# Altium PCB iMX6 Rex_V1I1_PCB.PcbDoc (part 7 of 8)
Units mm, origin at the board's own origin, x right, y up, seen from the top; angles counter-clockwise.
Board outline 70 x 40 mm, 12 copper layers (L1, L2, L3, L4, L5 (PWR), L6 (PWR), L7 (PWR), L8 (PWR), L9, L10, L11, L12), stack 1.566 mm thick; 473 components, 409 nets, 2294 pads, 1880 vias.
Unrouted connection lines stored in the file: 7.
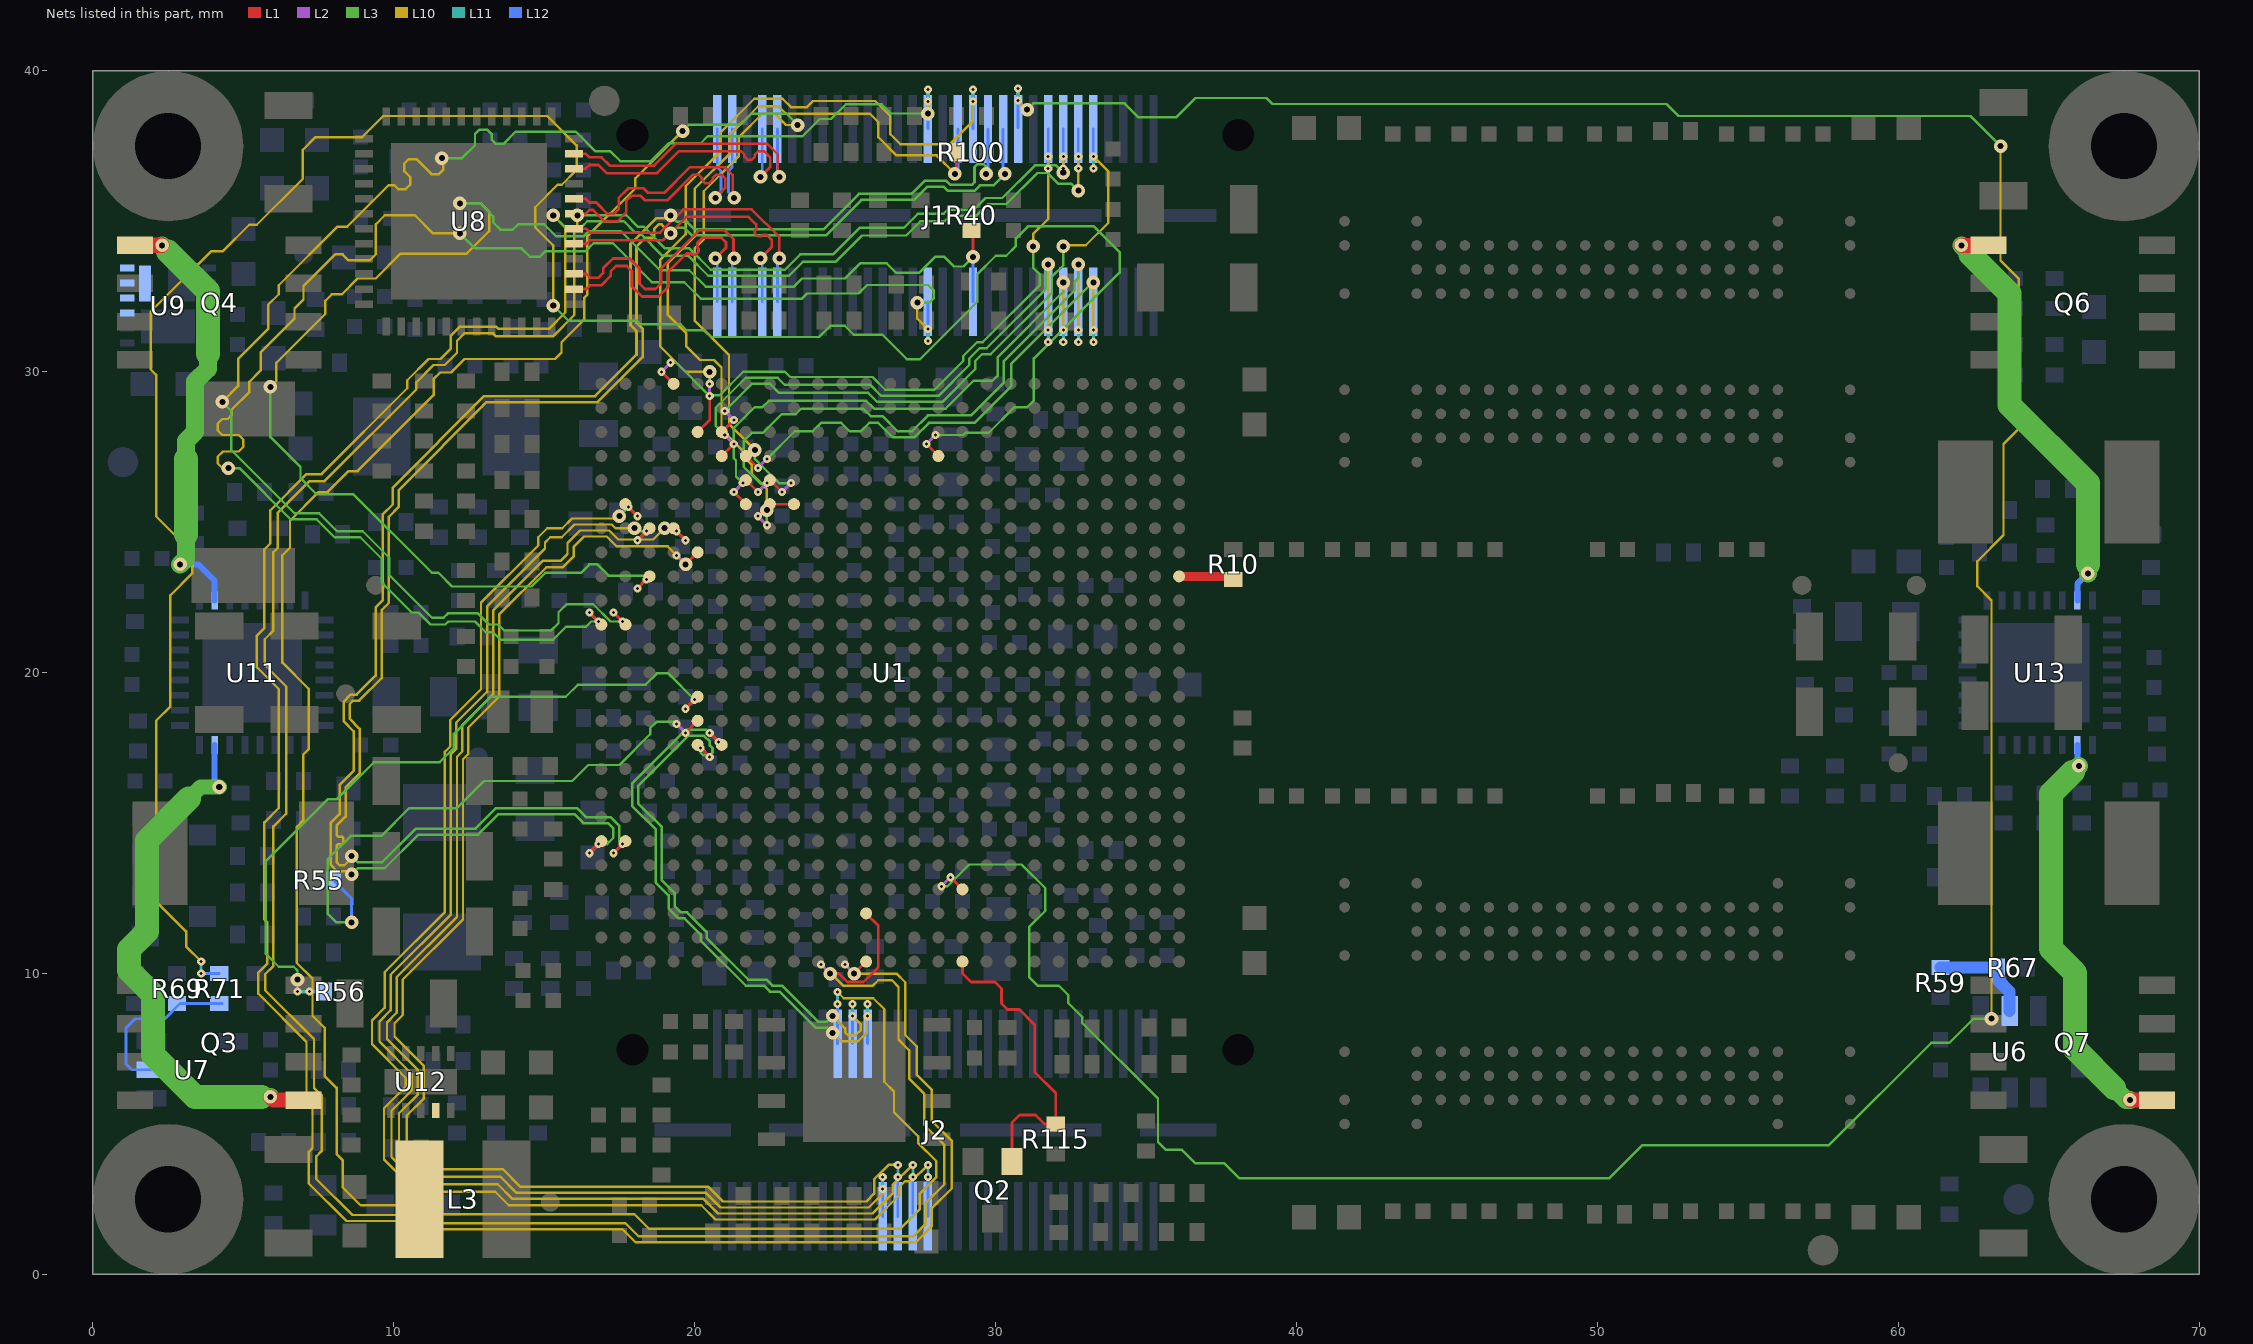
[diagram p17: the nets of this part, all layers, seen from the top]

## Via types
v1: diameter 0.45, hole 0.2, L1 to L12, tented both sides, 761 vias
v2: diameter 0.27, hole 0.1, L1 to L2, 305 vias
v3: diameter 0.27, hole 0.1, L2 to L3, 290 vias
v4: diameter 0.45, hole 0.2, L3 to L10, 196 vias
v5: diameter 0.27, hole 0.1, L11 to L12, 185 vias
v6: diameter 0.27, hole 0.1, L10 to L11, 142 vias
v7: diameter 0.45, hole 0.2, L3 to L10, tented both sides, 1 vias

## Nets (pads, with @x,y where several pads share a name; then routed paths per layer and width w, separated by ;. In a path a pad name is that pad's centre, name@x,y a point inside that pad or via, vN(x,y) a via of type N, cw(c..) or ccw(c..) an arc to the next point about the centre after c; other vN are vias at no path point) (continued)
SD3_DATA2: J1.31 U1.A15 | length 53.4
  L1 w0.093: v2(16.5,22) U1.A15@16.9,21.6
  L2 w0.1: v2(16.5,22) v3(16.8,21.7)
  L3 w0.08: v4(4.5,26.8) 4.871,26.8 6.571,25.1 7.434,25.1 8.034,24.5 8.886,24.5 9.6,23.786 9.6,23 10.6,22 10.817,22 11.217,21.6 11.713,21.6 11.813,21.7 12.7,21.7 13.057,21.343 13.3,21.343 13.543,21.1 15.3,21.1 15.725,21.525 16.388,21.525 16.563,21.7 v3(16.8,21.7) ; v4(12.2,34.6) 12.7,34.1 14.249,34.1 14.524,33.825 14.855,33.825 15.03,34 16.37,34 16.645,34.275 17.279,34.275 18.579,32.975 19.655,32.975 20.2,32.43 23.566,32.43 23.736,32.6 25.45,32.6 25.735,32.885 27.765,32.885 27.95,32.7 27.95,32.45 27.8,32.3 v4(27.4,32.3)
  L10 w0.08: v4(4.5,26.8) 4.3,26.8 4.15,26.95 4.15,27.18 4.32,27.35 4.85,27.35 5,27.5 5,27.75 4.85,27.9 4.3,27.9 4.15,28.05 4.15,28.28 4.3,28.43 4.48,28.43 4.625,28.575 4.625,28.755 5.2,29.33 5.2,29.67 5.575,30.045 5.575,30.645 6.7,31.77 6.7,32.1 7,32.4 7,32.85 8.05,33.9 8.3,33.9 8.5,33.7 9.2,33.7 9.4,33.9 9.4,34.9 9.7,35.2 10.7,35.2 11.3,34.6 v4(12.2,34.6) ; v4(27.4,32.3) 27.4,31.768 v6(27.75,31.418)
  L11 w0.1: v5(27.75,31.017) v6(27.75,31.418)
  L12 w0.093: v5(27.75,31.017) J1.31@27.75,32.33
SD3_DATA3: J1.32 U1.B15 | length 53.4
  L1 w0.093: v2(17.3,22) U1.B15@17.7,21.6
  L2 w0.1: v2(17.3,22) v3(17.6,21.7)
  L3 w0.08: v4(4.3,29) 4.6,28.7 4.6,27.404 6.704,25.3 7.517,25.3 8.117,24.7 8.969,24.7 9.85,23.819 9.85,23.25 11.275,21.825 11.655,21.825 11.8,21.97 12.8,21.97 13.17,21.6 13.47,21.6 13.67,21.4 15.23,21.4 15.475,21.645 15.475,22.005 15.745,22.275 16.628,22.275 17.203,21.7 v3(17.6,21.7) ; v4(11.6,37.1) 12.27,37.1 12.7,37.53 12.7,37.9 12.85,38.05 13.1,38.05 13.25,37.9 13.25,37.725 13.4,37.575 13.645,37.575 14.045,37.975 16.058,37.975 16.708,37.325 17.2,37.325 17.525,37 18.54,37 19.14,37.6 20.196,37.6 20.2,37.596 20.429,37.825 23.58,37.825 24.155,38.4 24.534,38.4 25.019,38.885 26.213,38.885 26.516,38.583 v4(27.75,38.583)
  L10 w0.08: v4(4.3,29) 4.825,29.525 4.825,30.425 5.825,31.425 5.825,32.225 6.175,32.575 6.175,32.875 8.125,34.825 8.455,34.825 9.83,36.2 10.02,36.2 10.15,36.07 10.4,36.07 10.55,36.22 10.55,36.47 10.35,36.67 10.35,36.92 10.5,37.07 10.75,37.07 11.25,36.57 11.5,36.57 11.65,36.72 11.65,37.05 v4(11.6,37.1) ; v4(27.75,38.583) v6(27.75,38.982)
  L11 w0.1: v6(27.75,38.982) v5(27.75,39.383)
  L12 w0.093: J1.32@27.75,38.07 v5(27.75,39.383)
SD3_WP: J1.25 R40.1 U1.C17 | length 51.6
  L1 w0.093: v2(18.1,22.8) U1.C17@18.5,23.2 ; R40.1@29.2,34.7 29.25,34.65 v1(29.25,33.82)
  L2 w0.1: v2(18.1,22.8) v3(18.4,23.1)
  L3 w0.08: v4(5.9,29.5) 5.9,27.83 6.9,26.83 6.9,26.465 7.44,25.925 8.662,25.925 11.262,23.325 11.48,23.325 11.94,22.865 14.583,22.865 15.033,23.315 16.218,23.315 16.503,23.6 16.77,23.6 17.145,23.225 18.275,23.225 v3(18.4,23.1) ; v4(12.2,35.6) 12.87,35.6 13.3,35.17 13.3,34.97 13.545,34.725 13.955,34.725 14.13,34.9 15,34.9 15.4,34.5 16.304,34.5 16.479,34.675 17.544,34.675 18.844,33.375 19.821,33.375 20.366,32.83 23.3,32.83 23.57,33.1 25,33.1 25.5,33.6 26.385,33.6 26.7,33.285 27.455,33.285 27.99,33.82 28.303,33.82 28.623,33.5 28.93,33.5 v1(29.25,33.82)
  L10 w0.08: v4(5.9,29.5) 6.1,29.7 6.1,30.3 7.725,31.925 7.725,32.355 7.945,32.575 8.275,32.575 8.8,33.1 9.4,33.1 10.225,33.925 12.425,33.925 13.175,34.675 13.175,35.325 12.9,35.6 v4(12.2,35.6)
  L12 w0.093: J1.25@29.25,32.33 v1(29.25,33.82)
SENSE_1V5: R59.1 R67.2 U6.5 | length 3.5
  L12 w0.4: R59.1@61.4,10.2 62.4,10.2 R67.2@63.3,10.2 63.3,9.8 63.7,9.4 U6.5@63.7,8.75
SW_3V0_SNVS: L3.1 U12.9
SW_EP: U9.3 U9.4 U9.5 U9.6 U9.14
TAMPER: R55.1 U1.E11 | length 19
  L1 w0.093: v2(19.7,18) U1.E11@20.1,18.4
  L2 w0.1: v3(19.4,18.3) v2(19.7,18)
  L3 w0.08: v1(8.6,11.7) 8.1,11.7 7.8,12 7.8,13.8 8.575,14.575 9.588,14.575 10.513,15.5 12.1,15.5 13,16.4 15.93,16.4 16.462,16.931 17.5,16.931 18.525,17.956 18.525,18.155 18.745,18.375 19.325,18.375 v3(19.4,18.3)
  L12 w0.093: R55.1@8,13.1 8.6,12.5 v1(8.6,11.7)
TEST_MODE: R56.2 U1.E12 | length 24.4
  L1 w0.093: v2(19.7,18.8) U1.E12@20.1,19.2
  L2 w0.1: v2(19.7,18.8) v3(20,19.1)
  L3 w0.08: v4(6.8,9.8) 6.8,10.1 6.675,10.225 6.175,10.225 5.75,10.65 5.75,13.737 7.8,15.787 8.1,15.787 9.338,17.025 11.525,17.025 12,17.5 12,17.966 13.234,19.2 15.717,19.2 16.117,19.6 18.37,19.6 18.745,19.975 19.125,19.975 v3(20,19.1)
  L10 w0.08: v6(6.8,9.4) v4(6.8,9.8)
  L11 w0.1: v6(6.8,9.4) v5(7.2,9.4)
  L12 w0.093: v5(7.2,9.4) R56.2@7.7,9.4
TRD0_N: J1.57 U8.3 | length 9.8
  L1 w0.09: U8.3@15.99,33.25 16.4,33.25 16.525,33.125 16.8,33.125 16.96,33.285 16.96,33.441 17.286,33.767 17.844,33.767 18.17,33.441 18.17,32.937 ; 18.17,32.93 18.35,32.75 18.7,32.75 18.88,32.93 18.88,33.434 20.146,34.7 21,34.7 21.292,34.408 21.292,33.787 v1(21.312,33.767)
  L12 w0.09: J1.57@21.25,32.33 21.25,33.705 v1(21.312,33.767)
TRD0_P: J1.59 U8.2 | length 9.8
  L1 w0.09: U8.2@15.99,32.75 16.4,32.75 16.525,32.875 16.904,32.875 17.21,33.181 17.21,33.337 17.39,33.517 17.74,33.517 17.92,33.337 17.92,32.826 18.246,32.5 18.804,32.5 19.13,32.826 19.13,33.33 19.73,33.93 19.887,33.93 19.93,33.887 20.03,33.887 20.13,33.987 20.13,34.087 20.087,34.13 20.087,34.287 20.25,34.45 20.896,34.45 21.043,34.304 21.043,34.122 v1(20.687,33.767)
  L12 w0.09: v1(20.687,33.767) 20.75,33.705 J1.59@20.75,32.33
TRD1_N: J1.51 U8.6 | length 9.8
  L1 w0.09: U8.6@15.99,34.75 16.4,34.75 16.525,34.625 18.852,34.625 19.627,35.4 21.896,35.4 22.813,34.484 v1(22.813,33.767)
  L12 w0.09: J1.51@22.75,32.33 22.75,33.705 v1(22.813,33.767)
TRD1_P: J1.53 U8.5 | length 9.8
  L1 w0.09: U8.5@15.99,34.25 16.4,34.25 16.525,34.375 18.955,34.375 19.73,35.15 21.793,35.15 22.043,34.9 22.043,34.743 22,34.7 22,34.6 22.1,34.5 22.2,34.5 22.243,34.543 22.4,34.543 22.563,34.38 22.563,34.142 v1(22.188,33.767)
  L12 w0.09: v1(22.188,33.767) 22.25,33.705 J1.53@22.25,32.33
TRD2_N: J1.58 U8.8 | length 9.8
  L1 w0.09: U8.8@15.99,35.75 16.375,35.75 16.5,35.625 16.729,35.625 17.104,35.25 17.325,35.25 17.475,35.4 17.475,35.775 17.8,36.1 18.304,36.1 18.454,35.95 18.996,35.95 19.846,36.8 21,36.8 21.263,36.538 21.263,35.83 v1(21.312,35.78)
  L12 w0.09: J1.58@21.25,38.07 21.25,36.8 21.125,36.675 21.125,35.967 v1(21.312,35.78)
TRD2_P: J1.60 U8.7 | length 9.8
  L1 w0.09: U8.7@15.99,35.25 16.375,35.25 16.5,35.375 16.625,35.375 17,35 17.429,35 17.725,35.296 17.725,35.671 17.904,35.85 18.2,35.85 18.35,35.7 19.1,35.7 19.95,36.55 20.131,36.55 20.246,36.435 20.246,36.37 20.346,36.27 20.496,36.27 20.596,36.37 20.596,36.435 20.711,36.55 20.896,36.55 21.013,36.434 21.013,36.105 v1(20.688,35.78)
  L12 w0.09: v1(20.688,35.78) 20.875,35.968 20.875,36.675 20.75,36.8 J1.60@20.75,38.07
TRD3_N: J1.52 U8.11 | length 9.8
  L1 w0.09: U8.11@15.99,37.25 16.375,37.25 16.5,37.125 16.904,37.125 17.179,36.85 18.65,36.85 19.38,37.58 22.404,37.58 22.762,37.221 22.762,36.53 v1(22.812,36.48)
  L12 w0.09: J1.52@22.75,38.07 22.75,36.542 v1(22.812,36.48)
TRD3_P: J1.54 U8.10 | length 9.8
  L1 w0.09: U8.10@15.99,36.75 16.375,36.75 16.5,36.875 16.8,36.875 17.075,36.6 18.754,36.6 19.484,37.33 21.535,37.33 21.65,37.215 21.65,37.15 21.75,37.05 21.9,37.05 22,37.15 22,37.215 22.115,37.33 22.3,37.33 22.512,37.118 22.512,36.805 v1(22.188,36.48)
  L12 w0.09: v1(22.188,36.48) 22.25,36.543 J1.54@22.25,38.07
UART1_CTS: J1.11 U1.G21 | length 21.8
  L1 w0.093: U1.G21@21.7,26.4 v2(22.1,26)
  L2 w0.1: v2(22.1,26) v3(22.4,26.3)
  L3 w0.08: v3(22.4,26.3) 22.17,26.3 21.625,26.845 21.625,27.7 21.9,27.975 22.272,27.975 22.885,28.588 23.358,28.588 23.545,28.775 25.6,28.775 25.85,28.525 26.245,28.525 26.745,28.025 27.225,28.025 27.75,28.55 29.18,28.55 30.278,29.648 30.278,30.358 32.625,32.705 32.625,32.988 32.75,33.113 v4(32.75,33.568)
  L10 w0.08: v6(32.75,31.39) v4(32.75,33.568)
  L11 w0.1: v5(32.75,30.99) v6(32.75,31.39)
  L12 w0.093: v5(32.75,30.99) J1.11@32.75,32.303
UART1_DCD: J1.16 U1.D25 | length 22.1
  L1 w0.093: v2(18.9,30) U1.D25@19.3,29.6
  L2 w0.1: v2(18.9,30) v3(19.2,30.3)
  L3 w0.08: v3(19.2,30.3) 19.397,30.3 20.482,29.215 20.829,29.215 21.614,30 23,30 23.175,29.825 25.911,29.825 26.336,29.4 27.967,29.4 28.925,30.358 28.925,30.521 29.386,30.983 29.571,30.983 31.475,32.886 31.475,33.23 31.25,33.455 v4(31.25,34.168)
  L10 w0.08: v4@31.25,34.205 31.25,34.58 31.75,35.08 v6(31.75,37.158)
  L11 w0.1: v5(31.75,36.758) v6(31.75,37.158)
  L12 w0.093: v5(31.75,36.758) J1.16@31.75,38.07
UART1_DSR: J1.9 U1.G22 | length 18.6
  L1 w0.093: U1.G22@21.7,27.2 v2(22.1,26.8)
  L2 w0.1: v2(22.1,26.8) v3(22.4,27.1)
  L3 w0.08: v3(22.4,27.1) 23.325,28.025 23.925,28.025 24.2,28.3 24.87,28.3 25.145,28.025 25.525,28.025 25.8,28.3 26.1,28.3 26.375,28.025 26.575,27.825 27.308,27.825 27.783,28.3 29.3,28.3 30.525,29.525 30.525,30.272 33.22,32.968 v7(33.25,32.968)
  L10 w0.08: v6(33.25,31.39) v7(33.25,32.968)
  L11 w0.1: v5(33.25,30.99) v6(33.25,31.39)
  L12 w0.093: v5(33.25,30.99) J1.9@33.25,32.303
UART1_DTR: J1.15 U1.F22 | length 19.9
  L1 w0.093: U1.F22@20.9,27.2 v2(21.3,27.6)
  L2 w0.1: v3(21,27.9) v2(21.3,27.6)
  L3 w0.08: v3(21,27.9) 20.7,28.2 20.7,28.803 21.697,29.8 22.759,29.8 22.996,29.562 25.841,29.562 26.203,29.2 28.1,29.2 29.125,30.225 29.125,30.438 29.469,30.783 29.704,30.783 31.675,32.754 ; 31.675,32.804 31.675,33.493 v4(31.75,33.568)
  L10 w0.08: v6(31.75,31.39) v4(31.75,33.568)
  L11 w0.1: v5(31.75,30.99) v6(31.75,31.39)
  L12 w0.093: v5(31.75,30.99) J1.15@31.75,32.303
UART1_RI: J1.10 U1.F23 | length 21.8
  L1 w0.093: U1.F23@20.9,28 v2(21.3,28.4)
  L2 w0.1: v3(21,28.7) v2(21.3,28.4)
  L3 w0.08: v3(21,28.7) 21.9,29.6 22.5,29.6 22.8,29.3 25.77,29.3 26.07,29 28.237,29 29.325,30.088 29.325,30.355 29.552,30.583 29.837,30.583 31.875,32.621 31.875,33.162 32.25,33.537 v4(32.25,34.168)
  L10 w0.08: v4(32.25,34.168) 32.288,34.205 33,34.205 33.75,34.955 33.75,36.657 v6(33.25,37.158)
  L11 w0.1: v5(33.25,36.758) v6(33.25,37.158)
  L12 w0.093: v5(33.25,36.758) J1.10@33.25,38.07
UART1_RTS: J1.13 U1.G20 | length 19.9
  L1 w0.093: v2(21.3,26) U1.G20@21.7,25.6
  L2 w0.1: v2(21.3,26) v3(21.6,26.3)
  L3 w0.08: v3(21.6,26.3) 21.375,26.525 21.375,27.055 21.3,27.13 21.3,28.13 21.995,28.825 22.255,28.825 22.468,29.037 25.7,29.037 25.962,28.775 28.345,28.775 29.27,29.7 29.9,29.7 30.078,29.878 30.078,30.491 32.25,32.663 v4(32.25,32.968)
  L10 w0.08: v6(32.25,31.39) v4(32.25,32.968)
  L11 w0.1: v5@32.25,30.99 v6(32.25,31.39)
  L12 w0.093: v5@32.25,30.99 J1.13@32.25,32.303
  other v5: 32.25,30.99
UART1_RXD: J1.14 U1.M3 | length 98.1
  L1 w0.093: v2(24.5,10) 24.8,10 25.085,9.715 25.615,9.715 26.1,10.2 26.1,11.6 U1.M3@25.7,12
  L2 w0.1: v3(24.2,10.3) v2(24.5,10)
  L3 w0.08: v4(16.1,35.2) 17.73,35.2 18.105,34.825 18.295,34.825 19.02,34.1 19.825,34.1 20.532,33.392 23,33.392 23.508,33.9 24.6,33.9 25.48,34.78 26.95,34.78 27.42,35.25 28.275,35.25 28.405,35.38 29.267,35.38 29.662,35.775 30.225,35.775 31.308,36.858 32.01,36.858 v4(32.25,36.618) ; v3(24.2,10.3) v2(24.5,10)
  L10 w0.08: v4(16.1,35.2) 16.1,34.8 16,34.7 16,31.887 15.288,31.175 13.4,31.175 13.3,31.275 12.345,31.275 12.1,31.03 12.1,30.63 11.695,30.225 11.325,30.225 10.75,29.65 10.75,29.417 7.7,26.367 7.2,26.367 6.15,25.317 6.15,24.15 6,24 6,21.4 5.713,21.113 5.713,20.251 6.425,19.538 6.425,15.317 6,14.892 6,10.25 5.725,9.975 5.725,9.445 7.35,7.82 7.35,6.2 7.6,5.95 7.6,4.1 7.425,3.925 7.425,3.175 8.625,1.975 10.861,1.975 11.136,1.7 17.7,1.7 18.132,1.268 27.268,1.268 27.675,1.675 27.675,2.375 28.3,3 28.3,4.3 27.625,4.975 27.625,6.011 27.125,6.511 27.125,7.453 26.775,7.803 26.775,9.555 26.555,9.775 26.1,9.775 25.925,9.6 24.936,9.6 24.536,10 v2(24.5,10) ; v4(32.25,36.618) v6(32.25,37.158)
  L11 w0.1: v5@32.25,36.758 v6(32.25,37.158)
  L12 w0.093: v5@32.25,36.758 J1.14@32.25,38.07
  other v4: 24.5,10
  other v5: 32.25,36.758
UART1_TXD: J1.12 U1.M1 | length 97.4
  L1 w0.093: v4(25.3,10) U1.M1@25.7,10.4
  L2 w0.1: v3(25,10.3) v4(25.3,10)
  L3 w0.08: v4(15.3,35.2) 15.675,34.825 16.255,34.825 16.43,35 17.647,35 18.022,34.625 18.162,34.625 18.937,33.85 19.792,33.85 20.449,33.192 23.133,33.192 23.59,33.65 24.683,33.65 25.563,34.53 27.033,34.53 27.503,35 28.308,35 28.488,35.18 29.35,35.18 29.745,35.575 30.358,35.575 31.39,36.608 31.73,36.608 32.095,36.243 32.525,36.243 v4(32.75,36.018) ; v3(25,10.3) v4(25.3,10)
  L10 w0.08: v4(15.3,35.2) 15.7,34.8 15.7,31.97 15.155,31.425 13.475,31.425 13.4,31.5 12.2,31.5 11.9,31.2 11.9,30.77 11.555,30.425 11.155,30.425 10.45,29.72 10.45,29.45 7.6,26.6 7.1,26.6 5.9,25.4 5.9,24.3 5.7,24.1 5.7,21.483 5.45,21.233 5.45,20.18 6.175,19.455 6.175,15.5 5.7,15.025 5.7,11.8 5.8,11.7 5.8,10.333 5.5,10.033 5.5,9.33 7.1,7.73 7.1,6 7.3,5.8 7.3,4.2 7.175,4.075 7.175,3.025 8.425,1.775 10.778,1.775 11.053,1.5 17.6,1.5 18.032,1.068 27.35,1.068 27.875,1.592 27.875,2.192 28.55,2.867 28.55,4.433 27.875,5.108 27.875,6.144 27.375,6.644 27.375,7.586 27,7.961 27,9.713 26.713,10 v4(25.3,10) ; v4(32.75,36.018) v6(32.75,37.158)
  L11 w0.1: v5(32.75,36.758) v6(32.75,37.158)
  L12 w0.093: v5(32.75,36.758) J1.12@32.75,38.07
  other v2: 25.3,10
UART2_CTS: J2.31 U1.B20 | length 49.7
  L1 w0.093: U1.B20@17.7,25.6 v2(18.1,25.2)
  L2 w0.1: v3(17.8,25.5) v2(18.1,25.2)
  L3 w0.08: v4(17.5,25.2) v3(17.8,25.5)
  L10 w0.08: v4(17.5,25.2) 17.425,25.125 15.925,25.125 15.6,24.8 15.1,24.8 14.8,24.5 14.8,24.229 12.9,22.329 12.9,19.449 11.875,18.424 11.875,17.545 11.7,17.37 11.7,12.049 9.7,10.049 9.7,8.87 9.275,8.445 9.275,7.655 10.4,6.53 10.4,6.249 9.675,5.524 9.675,3.821 10.746,2.75 13.371,2.75 13.821,2.3 20.219,2.3 20.694,1.825 25.994,1.825 26.8,2.631 26.8,2.9 27,3.1 27.207,3.1 v6(27.75,3.643)
  L11 w0.1: v5(27.75,3.243) v6(27.75,3.643)
  L12 w0.093: J2.31@27.75,1.93 v5(27.75,3.243)
UART2_RTS: J2.33 U1.C19 | length 48.8
  L1 w0.093: v2(18.1,24.4) U1.C19@18.5,24.8
  L2 w0.1: v2(18.1,24.4) v3(18.4,24.7)
  L3 w0.08: v4(18,24.8) 18.1,24.7 v3(18.4,24.7)
  L10 w0.08: v4(18,24.8) 17.37,24.8 17.245,24.925 16.008,24.925 15.583,24.5 15.2,24.5 15.025,24.325 15.025,24.121 13.1,22.196 13.1,19.366 12.075,18.341 12.075,17.462 11.9,17.287 11.9,11.966 9.9,9.966 9.9,8.787 9.525,8.412 9.525,7.738 10.6,6.663 10.6,6.116 9.925,5.441 9.925,3.904 10.829,3 13.454,3 13.934,2.52 20.282,2.52 20.777,2.025 25.911,2.025 26.58,2.695 26.58,2.98 27.243,3.643 v6(27.25,3.643)
  L11 w0.1: v5(27.25,3.243) v6(27.25,3.643)
  L12 w0.093: J2.33@27.25,1.93 v5(27.25,3.243)
UART2_RXD: J2.35 U1.E18 | length 49
  L1 w0.093: v4(19.7,23.6) U1.E18@20.1,24
  L2 w0.1: v3(19.4,23.9) v4(19.7,23.6)
  L3 w0.08: v3(19.4,23.9) v4(19.7,23.6)
  L10 w0.08: 10.425,5 10.425,5.275 ; v4(19.7,23.6) 19.1,24.2 17.404,24.2 17.079,24.525 16.324,24.525 15.975,24.176 15.975,23.862 15.613,23.5 15.07,23.5 13.5,21.93 13.5,19.2 12.475,18.175 12.475,17.296 12.3,17.121 12.3,11.8 10.3,9.8 10.3,8.621 10.025,8.346 10.025,7.904 11,6.929 11,5.85 10.425,5.275 ; v6(26.75,3.643) 26.443,3.643 25.965,3.165 25.965,2.685 25.705,2.425 20.943,2.425 20.448,2.92 14.2,2.92 13.62,3.5 10.995,3.5 10.425,4.07 10.425,5.275
  L11 w0.1: v5(26.75,3.243) v6(26.75,3.643)
  L12 w0.093: J2.35@26.75,1.93 v5(26.75,3.243)
  other v2: 19.7,23.6
UART2_TXD: J2.37 U1.D19 | length 47.8
  L1 w0.093: U1.D19@19.3,24.8 v2(19.7,24.4)
  L2 w0.1: v3(19.4,24.7) v2(19.7,24.4)
  L3 w0.08: v4(19,24.8) 19.1,24.7 v3(19.4,24.7)
  L10 w0.08: v4(19,24.8) 18.625,24.425 17.462,24.425 17.162,24.725 16.191,24.725 15.775,24.309 15.775,23.945 15.555,23.725 14.962,23.725 13.3,22.063 13.3,19.283 12.275,18.258 12.275,17.379 12.1,17.204 12.1,11.883 10.1,9.883 10.1,8.704 9.775,8.379 9.775,7.821 10.8,6.796 10.8,5.983 10.175,5.358 10.175,3.987 10.912,3.25 13.537,3.25 14.067,2.72 20.365,2.72 20.86,2.225 25.788,2.225 26.25,2.687 v6(26.25,2.842)
  L11 w0.1: v6(26.25,2.842) v5(26.25,3.243)
  L12 w0.093: J2.37@26.25,1.93 v5(26.25,3.243)
UGATE1_2V5: Q6.1 U13.15 | length 14.6
  L1 w0.5: v1(62.1,34.2) 62.995,34.2 Q6.1@63,34.205
  L3 w0.6: v1(62.1,34.2) 62.4,33.9 ; v1(66.3,23.3) 66.3,23.6
  L3 w0.8: 62.4,33.9 63.7,32.6 63.7,28.9 66.3,26.3 66.3,23.6
  L12 w0.2: U13.15@65.95,22.4 65.95,22.95 v1(66.3,23.3)
UGATE1_3V3: Q3.1 U11.15 | length 17.9
  L1 w0.5: v1(5.9,5.9) 6.005,5.795 Q3.1@7,5.795
  L3 w0.5: 3.2,15.825 3.575,16.2 v1(4.2,16.2)
  L3 w0.6: 5.6,5.9 v1(5.9,5.9)
  L3 w0.8: 3.2,15.825 1.8,14.425 1.8,11.4 1.2,10.8 1.2,10.1 2,9.3 2,7.3 3.4,5.9 5.6,5.9
  L12 w0.2: U11.15@4.05,17.6 4.05,16.35 v1(4.2,16.2)
UGATE2_1V5: Q7.1 U13.26 | length 14.3
  L1 w0.5: v1(67.7,5.8) 68.595,5.8 Q7.1@68.6,5.795
  L3 w0.6: 65.8,16.7 v1(66,16.9) ; 67.175,6.2 67.575,5.8 v1(67.7,5.8)
  L3 w0.8: 65.8,16.7 65.075,15.975 65.075,10.825 65.875,10.025 65.875,7.5 67.175,6.2
  L12 w0.2: U13.26@65.95,17.6 65.95,16.95 v1(66,16.9)
UGATE2_1V375: Q4.1 U11.26 | length 14.5
  L1 w0.5: Q4.1@1.4,34.205 v1@2.295,34.205
  L3 w0.6: v1(2.3,34.2) 2.5,34 ; v1(2.9,23.6) 3.1,23.8 3.1,24.6 ; 3.1,27.1 3.1,27.7 3.4,28 3.4,29.675 3.825,30.1 3.825,30.6
  L3 w0.8: 2.5,34 3.825,32.675 3.825,30.6 ; 3.1,24.6 3.1,27.1
  L12 w0.2: v1(2.9,23.6) 3.5,23.6 4.05,23.05 U11.26@4.05,22.4
USB0_ID: J1.20 U1.T4 | length 112
  L1 w0.093: v2(28.5,13.2) U1.T4@28.9,12.8
  L2 w0.1: v3(28.2,12.9) v2(28.5,13.2)
  L3 w0.08: v3(28.2,12.9) 28.403,12.9 29.128,13.625 30.867,13.625 31.65,12.842 31.65,12.08 31.115,11.545 31.115,9.88 31.395,9.6 32.1,9.6 32.414,9.286 32.414,9.026 32.875,8.565 32.875,8.368 35.4,5.843 35.4,4.4 35.652,4.148 36.183,4.148 36.63,3.7 37.595,3.7 38.095,3.2 50.4,3.2 51.5,4.3 57.7,4.3 61.1,7.7 61.7,7.7 62.5,8.5 v4(63.1,8.5) ; v4(31.05,38.71) 31.257,38.918 34.288,38.918 34.75,38.455 36,38.455 36.645,39.1 39,39.1 39.2,38.9 52.3,38.9 52.7,38.5 62.4,38.5 v4(63.4,37.5)
  L10 w0.08: v6(30.75,39.01) v4(31.05,38.71) ; v4(63.1,8.5) 63.1,22.4 62.625,22.875 62.625,23.7 63.5,24.575 63.5,27.6 64,28.1 64,33.1 63.4,33.7 v4(63.4,37.5)
  L11 w0.1: v6(30.75,39.01) v5(30.75,39.41)
  L12 w0.093: J1.20@30.75,38.098 v5(30.75,39.41)
USB0_N: J1.22 U1.B6 | length 55.4
  L1 w0.101: v2(17.3,14) U1.B6@17.7,14.4
  L2 w0.1: v2(17.3,14) v3(17.6,14.3)
  L3 w0.085: v4(8.6,13.9) 8.8,13.7 9.617,13.7 10.737,14.82 12.717,14.82 13.397,15.5 16.083,15.5 16.383,15.2 17.2,15.2 17.5,14.9 17.5,14.4 v3(17.6,14.3) ; v4(19.2,34.6) 19.383,34.783 19.667,34.783 19.915,34.535 24.363,34.535 25.54,35.712 27.29,35.712 27.725,36.148 28.28,36.148 28.415,36.012 29.295,36.012 29.48,36.197 29.93,36.197 v1(30.312,36.58)
  L10 w0.085: v4(8.6,13.9) 8.6,13.841 8.359,13.6 8.2,13.6 8.1,13.7 8.1,14.25 8.15,14.3 8.275,14.3 8.325,14.35 8.325,14.5 8.275,14.55 8.15,14.55 8.1,14.6 8.1,14.917 8.4,15.217 8.4,16.187 8.868,16.654 8.868,18.135 8.532,18.47 8.532,18.95 8.65,19.068 8.85,19.068 9.6,19.817 9.6,22.084 9.833,22.317 9.833,25.18 10.168,25.515 10.168,26.068 13.089,28.989 16.772,28.989 18.268,30.485 18.268,31.432 18.068,31.632 18.068,34.165 18.351,34.449 18.599,34.449 18.653,34.503 18.653,34.75 18.803,34.9 18.9,34.9 v4(19.2,34.6)
  L12 w0.101: J1.22@30.25,38.07 30.25,36.642 v1(30.312,36.58)
USB0_P: J1.24 U1.A6 | length 55.4
  L1 w0.101: v2(16.5,14) U1.A6@16.9,14.4
  L2 w0.1: v2(16.5,14) v3(16.8,14.3)
  L3 w0.085: v4(8.6,13.3) 8.8,13.5 9.7,13.5 10.82,14.62 12.8,14.62 13.48,15.3 16,15.3 16.3,15 17.117,15 17.3,14.817 17.3,14.514 17.086,14.3 v3(16.8,14.3) ; v4(19.2,35.2) 19.417,34.983 19.75,34.983 19.998,34.735 24.28,34.735 25.457,35.912 27.207,35.912 27.643,36.348 28.363,36.348 28.498,36.212 29.212,36.212 29.3,36.3 29.3,36.8 29.4,36.9 29.6,36.9 29.688,36.812 v1(29.688,36.58)
  L10 w0.085: v4(8.6,13.3) 8.5,13.4 8.117,13.4 7.9,13.617 7.9,15 8.2,15.3 8.2,16.27 8.668,16.737 8.668,18.052 8.332,18.387 8.332,19.032 8.568,19.268 8.768,19.268 9.4,19.9 9.4,22.167 9.633,22.4 9.633,25.263 9.968,25.598 9.968,26.15 13.006,29.189 16.689,29.189 18.068,30.568 18.068,31.35 17.868,31.55 17.868,34.248 18.72,35.1 19.1,35.1 v4(19.2,35.2)
  L12 w0.101: v1(29.688,36.58) 29.75,36.642 J1.24@29.75,38.07
USB0_PWR_EN: J1.26 U1.E23 | length 24.8
  L1 w0.093: U1.E23@20.1,28 20.5,28.4 v2(20.5,29.2)
  L2 w0.1: v2(20.5,29.2) v3(20.5,29.6)
  L3 w0.08: v3(20.5,29.6) v4(20.5,30)
  L10 w0.08: v4(20.5,30) 19.7,30 18.85,30.85 18.85,33.72 19.7,34.57 19.7,36.166 20.87,37.335 20.87,37.966 21.979,39.075 22.921,39.075 23.199,38.797 23.728,38.797 23.93,39 26,39 26.5,38.5 26.5,37.9 26.832,37.568 28.488,37.568 29.25,38.33 v6(29.25,38.982)
  L11 w0.1: v6(29.25,38.982) v5(29.25,39.383)
  L12 w0.093: J1.26@29.25,38.07 v5(29.25,39.383)
USB1_N: J2.40 U1.F10 | length 20.4
  L1 w0.101: v2(20.5,18) U1.F10@20.9,17.6
  L2 w0.1: v2(20.5,18) v3(20.8,17.7)
  L3 w0.085: v3(20.8,17.7) 20.4,18.1 19.7,18.1 17.922,16.322 17.922,15.575 18.7,14.797 18.7,13.032 19.132,12.6 19.132,12.165 19.465,11.832 19.668,11.832 20.2,11.3 20.2,11.097 21.697,9.6 22.3,9.6 22.5,9.4 22.817,9.4 24.017,8.2 24.418,8.2 v4(24.588,8.03)
  L10 w0.085: v4(24.588,8.03) 24.868,7.75 25.433,7.75 25.725,8.042 25.725,8.557 v6(25.75,8.582)
  L11 w0.1: v6(25.75,8.582) v5(25.75,8.983)
  L12 w0.101: J2.40@25.75,7.67 v5(25.75,8.983)
USB1_P: J2.42 U1.E10 | length 20.3
  L1 w0.101: U1.E10@20.1,17.6 v2(20.5,17.2)
  L2 w0.1: v3(20.2,17.5) v2(20.5,17.2)
  L3 w0.085: v3(20.2,17.5) 20.2,17.35 20.3,17.25 20.5,17.25 20.593,17.343 20.593,17.493 20.508,17.579 20.508,17.71 20.317,17.9 19.783,17.9 18.122,16.24 18.122,15.658 18.9,14.88 18.9,13.115 19.332,12.683 19.332,12.248 19.548,12.032 19.75,12.032 20.4,11.383 20.4,11.18 21.78,9.8 22.383,9.8 22.583,9.6 22.9,9.6 24.1,8.4 24.395,8.4 v4(24.588,8.592)
  L10 w0.085: v4(24.588,8.592) 25,8.18 25,8.05 25.1,7.95 25.35,7.95 25.525,8.125 25.525,8.308 v6(25.25,8.583)
  L11 w0.1: v6(25.25,8.583) v5(25.25,8.983)
  L12 w0.101: J2.42@25.25,7.67 v5(25.25,8.983)
USB1_PWR_EN: J2.44 U1.H21 | length 96.5
  L1 w0.093: U1.H21@22.5,26.4 v2(22.9,26)
  L2 w0.1: v2(22.9,26) v3(23.2,26.3)
  L3 w0.08: v4(19.6,38) 19.808,38.208 21.523,38.208 21.89,38.575 23.05,38.575 v4(23.425,38.2) ; v4(22,27.4) 22,27.097 22.512,26.585 22.518,26.585 22.803,26.3 v3(23.2,26.3)
  L10 w0.08: v4(19.6,38) 18.025,36.425 18.025,36.095 16.425,34.495 16.425,32.555 16.325,32.455 16.325,31.729 15.575,30.979 15.575,30.645 15.355,30.425 12.35,30.425 11.9,29.975 11.545,29.975 11.325,29.755 11.325,29.225 8.8,26.7 8.5,26.7 7.8,26 7.5,26 6.55,25.05 6.55,24.15 6.3,23.9 6.3,20.334 7.175,19.459 7.175,17.458 6.987,17.27 6.987,15.088 6.775,14.875 6.775,10.355 7.3,9.83 7.3,8.6 7.7,8.2 7.7,6.6 8.1,6.2 8.1,4 8.3,3.8 8.3,2.9 8.9,2.3 10.819,2.3 11.119,2 18,2 18.475,1.525 26.838,1.525 27.475,2.162 27.475,2.675 28.035,3.235 28.035,3.761 27.425,4.371 27.425,4.592 26.625,5.392 26.625,6.081 26.3,6.406 26.3,8.818 25.938,9.18 24.953,9.18 v6(24.75,9.383) ; v4(22,27.4) 21.141,28.259 21.141,30.559 20,31.7 20,34.1 20.3,34.4 20.3,36 21.47,37.17 21.47,37.8 22.245,38.575 22.655,38.575 23.03,38.2 v4(23.425,38.2)
  L11 w0.1: v5(24.75,8.983) v6(24.75,9.383)
  L12 w0.093: J2.44@24.75,7.67 v5(24.75,8.983)
USB_OC: J1.28 R100.1 U1.H20 U1.J20 | length 28.6
  L1 w0.093: v2(22.1,25.2) U1.H20@22.5,25.6 U1.J20@23.3,25.6 ; v1(28.65,36.58) 28.7,36.63 R100.1@28.7,37.3
  L2 w0.1: v2(22.1,25.2) v3(22.4,24.9)
  L3 w0.08: v3(22.4,24.9) v4(22.4,25.4)
  L10 w0.08: v4(22.4,25.4) 22.4,26.1 21.9,26.6 21.9,26.9 21.625,27.175 21.625,27.345 20.891,28.078 20.891,30.139 20.639,30.391 20.178,30.391 19.725,30.845 19.725,31.275 19.1,31.9 19.1,33.6 20,34.5 20,36.083 21.17,37.253 21.17,37.883 22.112,38.825 22.788,38.825 23.038,38.575 25.825,38.575 26.1,38.3 26.1,37.8 26.71,37.19 28.04,37.19 v1(28.65,36.58)
  L12 w0.093: v1(28.65,36.58) 28.75,36.68 J1.28@28.75,38.07
USER_LED: Q2.1 R115.1 U1.T1 | length 10.2
  L1 w0.093: U1.T1@28.9,10.4 28.9,9.997 29.182,9.715 29.985,9.715 30.2,9.5 30.2,9 30.4,8.8 30.405,8.805 30.795,8.805 31.3,8.3 31.3,6.725 32,6.025 R115.1@32,5 31.63,5 31.33,5.3 30.8,5.3 30.55,5.05 Q2.1@30.55,3.95
WD_OUT: R71.1 U1.R22 | length 81.9
  L1 w0.093: v2(27.7,27.6) U1.R22@28.1,27.2
  L2 w0.1: v2(27.7,27.6) v3(28,27.9)
  L3 w0.08: v4(15.3,32.2) 15.8,31.7 18.075,31.7 18.2,31.575 19.538,31.575 19.738,31.375 20.33,31.375 20.55,31.155 24.137,31.155 24.512,31.53 24.988,31.53 25.288,31.23 26.239,31.23 27.051,30.418 27.489,30.418 29.4,32.329 29.4,33.25 30.005,33.855 30.355,33.855 30.675,34.175 30.675,34.431 31.074,34.83 33.27,34.83 34.125,33.975 34.125,33.295 31.275,30.445 31.275,29.045 31.055,28.825 30.625,28.825 29.775,27.975 29,27.975 28.925,27.9 v3(28,27.9)
  L10 w0.08: v6(3.6,10.4) 3.1,10.9 3.1,11.4 2.1,12.4 2.1,18.4 2.575,18.875 2.575,22.575 3.3,23.3 3.3,24 2.1,25.2 2.1,29.9 1.925,30.075 1.925,32 3.925,34 4.313,34 5.198,34.885 5.448,34.885 6.975,36.412 6.975,37.375 7.4,37.8 8.95,37.8 9.65,38.5 15.1,38.5 16.075,37.525 16.075,36.705 15.585,36.215 15.445,36.215 14.7,35.47 14.7,34.8 15.3,34.2 v4(15.3,32.2)
  L11 w0.1: v5(3.6,10) v6(3.6,10.4)
  L12 w0.093: v5(3.6,10) R71.1@4.2,10
WD_OUT_R: R69.1 R71.2 U7.2 | length 5.7
  L12 w0.093: U7.2@1.95,6.8 1.3,6.8 1.1,7 1.1,8.2 1.4,8.5 2.4,8.5 2.9,9 R71.2@4.3,9
ZQPAD: R10.1 U1.AE17 | length 1.8
  L1 w0.3: U1.AE17@36.1,23.2 37.8,23.2 R10.1@37.9,23.1
pads on no net: FID1.1 FID2.1 FID3.1 FID4.1 J1.49 J1.65 J1.66 J2.65 J2.66 U1.A9 U1.A10 U1.A11 U1.A16 U1.A20 U1.A21 U1.AA1 U1.AA2 U1.AA3 U1.AA4 U1.AA11 U1.AB1 U1.AB2 U1.AB17 U1.AD17 U1.B8 U1.B9 U1.B10 U1.B11 U1.B16 U1.B17 U1.B19 U1.B21 U1.C5 U1.C8 U1.C13 U1.C15 U1.C16 U1.C20 U1.C25 U1.D1 U1.D2 U1.D4 U1.D5 U1.D13 U1.D15 U1.D18 U1.D20 U1.E1 U1.E2 U1.E3 U1.E4 U1.E13 U1.E16 U1.E19 U1.E22 U1.E24 U1.E25 U1.F1 U1.F2 U1.F3 U1.F4 U1.F13 U1.F15 U1.F17 U1.F24 U1.F25 U1.G1 U1.G2 U1.G4 U1.G23 U1.G25 U1.H1 U1.H2 U1.H3 U1.H4 U1.H22 U1.H23 U1.H24 U1.J19 U1.J21 U1.J22 U1.J23 U1.J24 U1.J25 U1.K20 U1.K21 U1.K22 U1.K23 U1.K24 U1.K25 U1.L1 U1.L3 U1.L4 U1.L6 U1.L20 U1.L21 U1.L22 U1.L23 U1.L24 U1.L25 U1.M2 U1.M4 U1.M5 U1.M6 U1.M20 U1.M21 U1.M22 U1.M23 U1.M24 U1.M25 U1.N2 U1.N19 U1.N20 U1.N21 U1.N22 U1.N23 U1.N24 U1.N25 U1.P1 U1.P4 U1.P5 U1.P6 U1.P20 U1.P21 U1.P25 U1.R1 U1.R2 U1.R3 U1.R4 U1.R5 U1.R6 U1.R7 U1.R20 U1.R21 U1.R23 U1.R24 U1.T2 U1.T6 U1.T20 U1.T22 U1.T23 U1.T24 U1.T25 U1.U6 U1.U7 U1.U20 U1.U22 U1.U25 U1.V5 U1.V6 U1.V24 U1.W5 U1.W6 U1.W20 U1.W21 U1.W23 U1.W24 U1.Y1 U1.Y2 U1.Y3 U1.Y4 U2.J1 U2.J9 U2.L1 U2.L9 U2.MECH01 U2.MECH02 U2.MECH03 U2.MECH04 U2.MECH05 U2.MECH06 U2.MECH07 U2.MECH08 U2.MECH09 U2.MECH10 U2.MECH11 U2.MECH12 U2.MECH13 U2.MECH14 U2.MECH15 U2.MECH16 U3.J1 U3.J9 U3.L1 U3.L9 U3.MECH01 U3.MECH02 U3.MECH03 U3.MECH04 U3.MECH05 U3.MECH06 U3.MECH07 U3.MECH08 U3.MECH09 U3.MECH10 U3.MECH11 U3.MECH12 U3.MECH13 U3.MECH14 U3.MECH15 U3.MECH16 U4.J1 U4.J9 U4.L1 U4.L9 U4.MECH01 U4.MECH02 U4.MECH03 U4.MECH04 U4.MECH05 U4.MECH06 U4.MECH07 U4.MECH08 U4.MECH09 U4.MECH10 U4.MECH11 U4.MECH12 U4.MECH13 U4.MECH14 U4.MECH15 U4.MECH16 U5.J1 U5.J9 U5.L1 U5.L9 U5.MECH01 U5.MECH02 U5.MECH03 U5.MECH04 U5.MECH05 U5.MECH06 U5.MECH07 U5.MECH08 U5.MECH09 U5.MECH10 U5.MECH11 U5.MECH12 U5.MECH13 U5.MECH14 U5.MECH15 U5.MECH16 U8.43 U11.9 U13.9

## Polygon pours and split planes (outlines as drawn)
GND on L12 "L12-GND" (solid, pour order 138): 5.1,38.5 5.4,38.2 5.4,37.3 6.4,37.3 6.4,39.4 5.2,39.4 5.1,39.3
+1V2_ETH on L12 "L12-+1V2_ETH" (solid, pour order 137): 27 vertices, not listed, extent 2.5,31.5 7.9,36.5
GND on L12 "L12-GND 1" (solid, pour order 197): 19.3,19.9 20,19.9 20,23.8 19.9,23.9 19.9,24.5 19.3,24.5 19.3,24.3 18.7,23.7 18.7,23.3 18.4,23 18.4,22.4 18.6,22.2 18.6,22 19.3,21.3
+3V3 on L12 "L12-+3V3" (solid, pour order 198): 18 vertices, not listed, extent 20.3,21.8 21.5,24.5
GND on L12 "L12-GND 2" (solid, pour order 134): 1.6,32.1 3.4,32.1 3.4,31.1 4.1,31.1 4.1,29.2 2.7,29.2 2.7,30 2.9,30 2.9,30.6 2.6,30.9 1.6,30.9
SW_EP on L12 "L12-SW_EP" (solid, pour order 135): 0.9,33.6 2,33.6 2,32.3 1.4,32.3 1.4,31.8 0.9,31.8 0.9,33.6
+3V3 on L12 "L12-+3V3 1" (solid, pour order 139): 0.9,31.1 1.4,31.1 1.4,30.5 1.8,30.1 1.9,30 2.1,30 2.1,29.1 1.6,28.6 1.2,28.6 1.1,28.7 1.1,28.8 1.1,30 0.9,30.2 0.9,31.1
GND on L12 "L12-GND 3" (solid, pour order 140): 18 vertices, not listed, extent 9.4,31.2 13,35.4
GND on L12 "L12-GND 4" (solid, pour order 141): 13.7,32.1 16.3,32.1 16.3,32.7 15.8,32.7 15.6,32.9 15.6,34.7 15,34.7 14.7,34.4 13.5,34.4 13.5,33.5 13.7,33.3
+1V2_ETH_AVDDL on L12 "L12-+1V2_ETH_AVDDL" (solid, pour order 142): 16,34.1 16.4,34.1 16.6,33.9 16.6,33.8 16.7,33.7 16.9,33.7 17,33.8 17,36.8 16.8,37 16,37 16,34.1
GND on L12 "L12-GND 5" (solid, pour order 143): 12.7,36.9 14.4,36.9 14.5,36.8 14.5,35.9 14.7,35.7 14.9,35.7 15,35.6 15,35.4 15.6,35.4 15.6,37.3 15.7,37.4 16.5,37.4 16.5,38 12.6,38 12.6,37
+VIN on L12 "L12-+VIN" (solid, pour order 150): 8.8,18.5 10.2,18.5 10.2,19.9 9.3,19.9 9.3,19.8 9,19.5 8.7,19.5 8.6,19.4 8.6,18.7
GND on L12 "L12-GND 6" (solid, pour order 151): 11.2,19.9 12.1,19.9 12.1,18.5 11.7,18.1 11.3,18.1 11.2,18.2
GND on L12 "L12-GND 7" (solid, pour order 152): 21 vertices, not listed, extent 13.7,19.4 17.1,23.7
GND on L12 "L12-GND 8" (solid, pour order 154): 7.7,11 8.2,11 8.2,10.7 8.8,10.1 9.4,10.1 9.5,10 9.5,8.8 9.4,8.7 8.5,8.7 8.4,8.8 8.4,9.8 7.9,10.3 7.8,10.3 7.7,10.4
+3V3 on L12 "L12-+3V3 2" (solid, pour order 155): 4.1,5.5 5.2,5.5 5.3,5.6 5.3,6.1 5.6,6.4 5.7,6.5 6.2,6.5 6.2,7.1 4.7,7.1 4.5,6.9 4.1,6.5 4.1,5.5
GND on L12 "L12-GND 9" (solid, pour order 199): 15.8,24.5 16.6,24.5 16.7,24.6 16.7,24.8 17,25.1 17.7,25.1 17.7,25.6 16.9,25.6 16.6,25.4 15.3,25.4 15.2,25.3 15.2,25.1 15.8,24.5
+1V375_VDDSOC_IN on L12 "L12-+1V375_VDDSOC_IN" (solid, pour order 201): 20.3,29.2 20.3,28.4 20.1,28.2 18,28.2 17.9,28.3 17.9,29.5 18,29.6 19,29.6 19.2,29.4 20.1,29.4
+1V375 on L12 "L12-+1V375" (solid, pour order 202): 18.9,30.2 18.9,31.1 18.7,31.3 16.8,31.3 16.7,31.2 16.7,30.7 16.8,30.6 17.7,30.6 18.1,30.2
GND on L12 "L12-GND 10" (solid, pour order 203): 23 vertices, not listed, extent 23.9,27.3 27.4,30.2
+VDDPU on L12 "L12-+VDDPU" (solid, pour order 206): 38 vertices, not listed, extent 22.7,23.4 26.9,25.5
+1V375_VDDSOC_IN on L12 "L12-+1V375_VDDSOC_IN 1" (solid, pour order 207): 28.1,25.9 28.1,26.7 28.8,26.7 29.1,27 29.4,27 29.5,26.9 29.5,26.6 29.4,26.5 29.4,26.1 29.2,25.9
+1V5_DDR on L12 "L12-+1V5_DDR" (solid, pour order 208): 31.5,27.5 31.5,26.7 31.2,26.4 31.2,25.7 31.1,25.6 30.7,25.6 30.6,25.7 30.1,25.7 29.7,26.1 29.7,26.9 30.3,26.9 30.6,27.2 30.6,27.5
GND on L12 "L12-GND 11" (solid, pour order 209): 35 vertices, not listed, extent 28.5,23.4 33.5,27.5
+1V5_DDR on L12 "L12-+1V5_DDR 1" (solid, pour order 210): 30 vertices, not listed, extent 29.1,21.8 33.3,24.6
GND on L12 "L12-GND 12" (solid, pour order 211): 20 vertices, not listed, extent 31.5,20.8 34.3,23.2
GND on L12 "L12-GND 13" (solid, pour order 205): 26.5,23.3 26.5,23.8 26.9,23.8 27.1,24 27.1,24.5 27.2,24.6 27.8,24.6 28,24.4 28,22.4 27.4,22.4 27.4,23.1 27.2,23.3
+1V5_DDR on L12 "L12-+1V5_DDR 2" (solid, pour order 216): 31.6,15.3 32.2,15.3 32.2,15.9 31.9,16.2 31.9,16.3 31.9,16.9 31.3,16.9 31.3,16.3 31.6,16 31.6,15.3
GND on L12 "L12-GND 14" (solid, pour order 213): 28 vertices, not listed, extent 21.8,21 25.6,22.7
+1V2_VDD_ARM_CAP on L12 "L12-+1V2_VDD_ARM_CAP" (solid, pour order 217): 60 vertices, not listed, extent 21.6,17.2 26.3,20.6
GND on L12 "L12-GND 15" (solid, pour order 218): 21 vertices, not listed, extent 18,17.8 22.2,18.8
GND on L12 "L12-GND 16" (solid, pour order 219): 13.5,14.7 13.7,14.7 14,14.4 15.4,14.4 15.4,15.3 15.3,15.4 14.2,15.4 13.8,15.8 13.8,16 13.7,16.1 13.5,16.1
GND on L12 "L12-GND 17" (solid, pour order 220): 31 vertices, not listed, extent 15.7,11.8 18.8,17.7
GND on L12 "L12-GND 18" (solid, pour order 221): 42 vertices, not listed, extent 23.6,15.1 27.9,19
+1V375 on L12 "L12-+1V375 1" (solid, pour order 222): 42 vertices, not listed, extent 24.8,13.2 30.5,17.7
GND on L12 "L12-GND 19" (solid, pour order 223): 23 vertices, not listed, extent 29.1,14.4 32.1,16.6
GND on L12 "L12-GND 20" (solid, pour order 224): 32.3,16.3 32.9,16.3 32.9,18.1 33.2,18.4 33.2,19.9 34.2,20.9 33.2,20.9 32.9,20.6 31.6,20.6 31.5,20.5 31.5,20.3 32.4,20.3 32.6,20.1 32.6,18.5 32.3,18.2
GND on L12 "L12-GND 21" (solid, pour order 225): 26.4,14.3 28.8,14.3 29.1,14 29.1,13.9 29.2,13.8 29.4,13.8 29.5,13.9 29.5,14.1 29.1,14.5 29.1,14.9 26.7,14.9 26.6,15 26.4,15
GND on L12 "L12-GND 22" (solid, pour order 226): 27 vertices, not listed, extent 18.8,11.5 20.6,14.2
GND on L12 "L12-GND 23" (solid, pour order 228): 17 vertices, not listed, extent 22.4,11.4 23.9,13.5
GND on L12 "L12-GND 24" (solid, pour order 229): 23.6,13.7 25.4,13.7 25.4,13.1 24.8,13.1 24.7,13 24.3,13 24.2,13.1 23.6,13.1 23.6,13.7
GND on L12 "L12-GND 25" (solid, pour order 230): 26 vertices, not listed, extent 27.6,9.3 33.1,12.7
GND on L12 "L12-GND 26" (solid, pour order 200): 30 vertices, not listed, extent 19.5,26.6 23.3,30.6
+1V375_VDDSOC_IN on L12 "L12-+1V375_VDDSOC_IN 2" (solid, pour order 212): 49 vertices, not listed, extent 21.7,21.8 27.9,23.7
+1V1_VDDSOC_CAP on L12 "L12-+1V1_VDDSOC_CAP" (solid, pour order 214): 23 vertices, not listed, extent 29.1,19.3 32.6,22.3
GND on L12 "L12-GND 27" (solid, pour order 231): 21 vertices, not listed, extent 26.6,21 29.5,22.2
+1V5_DDR on L12 "L12-+1V5_DDR 3" (solid, pour order 233): 63.6,33.4 66.1,33.4 66.9,32.6 66.9,31.7 66.1,31.7 66.1,32.5 65.8,32.8 63.6,32.8
GND on L12 "L12-GND 28" (solid, pour order 232): 63.6,29.6 66.5,29.6 66.9,30 66.9,31.1 66.1,31.1 66.1,30.3 66,30.2 63.6,30.2
+DDR_VREF on L12 "L12-+DDR_VREF" (solid, pour order 234): 17 vertices, not listed, extent 63.6,30.6 65.5,32.4
GND on L12 "L12-GND 29" (solid, pour order 235): 57.9,21 58.8,21 58.8,22.8 58.9,22.9 59.3,23.3 59.3,24.1 58.4,24.1 57.4,23.1 57.4,22.5 57.9,22
+1V5_DDR on L12 "L12-+1V5_DDR 4" (solid, pour order 215): 32.2,20.1 32.2,18.5 31.9,18.2 31.9,17.5 31.3,17.5 31.3,18.1 30.7,18.7 30.7,18.9 30.9,19.1 31.3,19.1 31.4,19.2 31.4,20.1
+3V0_ALWAYS on L12 "L12-+3V0_ALWAYS" (solid, pour order 136): 14.1,19.3 15.5,19.3 15.5,18.3 15,17.8 15,17.6 14.9,17.5 14.2,17.5 14.1,17.6
+3V3 on L12 "L12-+3V3 3" (solid, pour order 204): 23.9,26.9 26.5,26.9 26.5,26.3 26.2,26 25.8,26 25.5,26.3 25.1,26.3 24.7,25.9 24.3,25.9 23.9,26.3
+1V5_DDR on L1 "L1-+1V5_DDR" (solid, pour order 242): 63.4,12.2 63.4,15.1 64.3,16 64.3,17.1 63.4,18 63.4,19.4 63.1,19.7 59.7,19.7 59.7,16.8 61.3,15.2 61.3,12.2
+3V0_ALWAYS on L1 "L1-+3V0_ALWAYS" (solid, pour order 163): 18 vertices, not listed, extent 11.8,0.5 15.5,6
GND on L1 "L1-GND" (solid, pour order 169): 43 vertices, not listed, extent 16.7,11.8 21.1,16.2
+VIN on L1 "L1-+VIN" (solid, pour order 195): 17 vertices, not listed, extent 33.6,32 36.6,37.7
GND on L1 "L1-GND 1" (solid, pour order 190): 48 vertices, not listed, extent 21.9,15 31.5,17
GND on L1 "L1-GND 2" (solid, pour order 188): 30.9,19.3 31.2,19 31.4,19 31.5,19.1 31.5,19.3 31.4,19.4 31.4,19.8 31.9,20.3 31.9,20.5 31.8,20.6 31.6,20.6 30.9,19.9
GND on L1 "L1-GND 3" (solid, pour order 144): 7.3,39.3 7.3,38.4 5.3,38.4 5.1,38.6 5.1,39.2 5.3,39.4 7.3,39.4 7.3,39.3
+VIN on L1 "L1-+VIN 1" (solid, pour order 145): 7.6,33.9 7.6,34.7 7.3,35 7.3,36.3 7.6,36.6 7.6,37 7.5,37.1 5.7,37.1 5.6,37 5.6,34 5.7,33.9
GND on L1 "L1-GND 4" (solid, pour order 146): 0.8,33.3 0.8,31.3 3.2,31.3 3.3,31.4 3.3,33.2 3.2,33.3
PHASE2_1V375 on L1 "L1-PHASE2_1V375" (solid, pour order 147): 7,32.935 7,27.8 3.3,27.8 3.3,30 4.4,31.1 5.6,32.4 5.7,32.5 5.9,32.5 6.2,32.8 6.2,33.1 6.3,33.2 7,33.2
GND on L1 "L1-GND 5" (solid, pour order 149): 3.4,18 7.5,18 7.5,18.9 7.5,19.3 7.3,19.5 3.7,19.5 3.6,19.5 3.4,19.3 3.4,18
+3V3 on L1 "L1-+3V3" (solid, pour order 157): 6.8,12.3 8,11.1 8.7,11.1 8.9,10.9 9.2,10.6 10.2,10.6 10.2,17.2 9.7,17.2 9.6,17.3 8.7,18.2 8,18.2 7.7,17.9 7.7,17.7 6.8,16.8
GND on L1 "L1-GND 6" (solid, pour order 158): 9.3,18.9 11.5,18.9 11.7,18.7 11.7,17.8 11.7,17.7 11.5,17.5 10.3,17.5 10.2,17.5 9.9,17.8 9.7,18 9.3,18 9.3,18.9
GND on L1 "L1-GND 7" (solid, pour order 161): 5.1,0.6 7.9,0.6 7.9,1.3 7.7,1.5 5.3,1.5 5.1,1.3
SW_3V0_SNVS on L1 "L1-SW_3V0_SNVS" (solid, pour order 162): 11.5,5.7 11.5,4.9 11.7,4.7 11.7,0.5 10,0.5 10,4.5 10.9,4.5 11.3,4.9 11.3,5.7
GND on L1 "L1-GND 8" (solid, pour order 164): 12.9,7.6 15.3,7.6 15.3,6.6 12.9,6.6 12.9,7.6
GND on L1 "L1-GND 9" (solid, pour order 165): 6.4,6.8 7.6,6.8 7.6,8.7 7.5,8.8 7.3,8.8 7,9.1 6.6,9.1 6.4,8.9
GND on L1 "L1-GND 10" (solid, pour order 166): 8.3,7.1 8.9,7.1 8.9,8.1 9,8.2 9.5,8.7 9.5,9.9 9.4,10 9.3,10.1 8.1,10.1 8,10 8,8.2 8.3,7.9 8.3,7.1
+VIN on L1 "L1-+VIN 2" (solid, pour order 167): 11.5,7.1 10.8,7.1 10.8,9.5 11.1,9.8 12.7,9.8 13.1,9.4 13.1,8 13,7.9 12.6,7.9 12.4,8.1 11.9,8.1 11.5,7.7
GND on L1 "L1-GND 11" (solid, pour order 168): 13.6,17.2 13.7,17.1 13.7,14.7 13.6,14.6 13.5,14.6 13.3,14.4 13.3,13.3 13.5,13.1 13.6,13.1 13.7,13 13.7,11 13.3,10.6 12,10.6 12,17.2
+3V0_ALWAYS on L1 "L1-+3V0_ALWAYS 1" (solid, pour order 170): 23.4,16.6 23.5,16.7 23.5,16.9 23.4,17 22.6,17 22.4,17.2 22.3,17.3 22.2,17.4 22,17.4 21.9,17.3 21.9,17.1 22.4,16.6
+1V1_VDDSOC_CAP on L1 "L1-+1V1_VDDSOC_CAP" (solid, pour order 172): 28,17.4 28.8,17.4 29.1,17.1 29.5,17.1 29.9,17.5 29.9,17.7 29.8,17.8 29.6,17.8 29.4,17.6 29.2,17.6 29,17.8 28,17.8 27.9,17.7 27.9,17.5
+1V375 on L1 "L1-+1V375" (solid, pour order 171): 33 vertices, not listed, extent 23.9,16.3 29.9,17.3
+1V1_VDDSOC_CAP on L1 "L1-+1V1_VDDSOC_CAP 1" (solid, pour order 173): 28.8,19.8 29,19.8 29.2,20 29.4,20 29.6,19.8 29.8,19.8 29.9,19.9 29.9,20.9 29.5,21.3 29.1,21.3 28.8,21 28.7,20.9 28.7,19.9
+1V2_VDD_ARM_CAP on L1 "L1-+1V2_VDD_ARM_CAP" (solid, pour order 174): 48 vertices, not listed, extent 22.3,17.9 28.3,18.9
+1V2_VDD_ARM_CAP on L1 "L1-+1V2_VDD_ARM_CAP 1" (solid, pour order 175): 38 vertices, not listed, extent 22.3,19.5 28.3,20.5
+1V375 on L1 "L1-+1V375 1" (solid, pour order 176): 49 vertices, not listed, extent 22.3,20.3 28.3,21.3
GND on L1 "L1-GND 12" (solid, pour order 177): 20 vertices, not listed, extent 23.9,17.1 27.9,18.1
GND on L1 "L1-GND 13" (solid, pour order 178): 25 vertices, not listed, extent 22.3,19 25.9,19.7
GND on L1 "L1-GND 14" (solid, pour order 179): 18 vertices, not listed, extent 27.1,17.9 29.9,19.7
+3V3 on L1 "L1-+3V3 1" (solid, pour order 180): 19 vertices, not listed, extent 21.2,20.6 22,23.4
GND on L1 "L1-GND 15" (solid, pour order 181): 46 vertices, not listed, extent 22.3,21.1 29.9,22.1
+1V375_VDDSOC_IN on L1 "L1-+1V375_VDDSOC_IN" (solid, pour order 182): 52 vertices, not listed, extent 22.3,21.9 29.9,22.9
+VDDPU on L1 "L1-+VDDPU" (solid, pour order 183): 39 vertices, not listed, extent 22.3,23 27.5,23.7
GND on L1 "L1-GND 16" (solid, pour order 184): 52 vertices, not listed, extent 21.5,23 29.9,25
+3V3 on L1 "L1-+3V3 2" (solid, pour order 185): 31 vertices, not listed, extent 23.9,24.6 27.5,25.3
+1V5_DDR on L1 "L1-+1V5_DDR 1" (solid, pour order 186): 33 vertices, not listed, extent 27.9,16.6 31,24.5
GND on L1 "L1-GND 17" (solid, pour order 187): 32 vertices, not listed, extent 28.7,21.4 31.8,25.3
GND on L1 "L1-GND 18" (solid, pour order 189): 31.3,17.4 31.4,17.4 31.5,17.5 31.5,18.5 31.4,18.6 31.2,18.6 30.8,18.2 30.8,17.8 31.2,17.4 31.3,17.4
+2V5_VDDHIGH_VPH on L1 "L1-+2V5_VDDHIGH_VPH" (solid, pour order 191): 22.3,17.5 22.4,17.4 22.6,17.4 22.8,17.6 23,17.6 23.2,17.4 23.4,17.4 23.5,17.5 23.5,17.7 23.1,18.1 22.7,18.1 22.3,17.7
GND on L1 "L1-GND 19" (solid, pour order 192): 19 vertices, not listed, extent 22.6,35.1 24.5,37.6
GND on L1 "L1-GND 20" (solid, pour order 193): 17 vertices, not listed, extent 31.9,35 34.2,36.7
GND on L1 "L1-GND 21" (solid, pour order 194): 37.8,32 38.7,32 39,32.3 39,32.8 39.8,33.6 39.8,35.9 38.9,36.8 37.6,36.8 37.5,36.7 37.5,32.3
GND on L1 "L1-GND 22" (solid, pour order 196): 22.1,4.3 23.6,4.3 23.8,4.5 23.8,5.3 23.6,5.3 23.4,5.1 23,5.1 22.6,4.7 22.1,4.7
GND on L1 "L1-GND 23" (solid, pour order 236): 62.7,39.4 64.8,39.4 64.9,39.3 64.9,38.6 64.8,38.5 64.8,38.4 62.7,38.4 62.7,39.4
+VIN on L1 "L1-+VIN 3" (solid, pour order 160): 0.8,6.1 0.8,5.4 4.1,5.4 5.4,4.1 5.4,3.4 6.3,2.5 7.3,2.5 7.4,2.6 7.4,4.6 7.3,4.7 6.4,4.7 4.6,6.5 2.7,6.5 2.3,6.1
GND on L1 "L1-GND 24" (solid, pour order 238): 63.6,33.3 63.6,31.3 62.1,31.3 61.9,31.5 61.9,32.9 61.9,33.1 62.1,33.3 63.5,33.3 63.6,33.3
+VIN on L1 "L1-+VIN 4" (solid, pour order 237): 17 vertices, not listed, extent 61.3,33.5 69.2,37.1
PHASE1_2V5 on L1 "L1-PHASE1_2V5" (solid, pour order 240): 68.8,24.3 68.7,24.2 66.8,24.2 65.8,25.2 65.8,31.2 67.8,33.3 68.6,33.3 68.6,28.3 68.8,28.1
GND on L1 "L1-GND 25" (solid, pour order 243): 55.9,17.4 56,17.3 56.8,17.3 57,17.3 57.5,17.8 57.8,18.1 57.8,19.6 56.4,19.6 56.1,19.3 55.9,19.1 55.9,17.4
GND on L1 "L1-GND 26" (solid, pour order 244): 56.5,20.4 57.8,20.4 57.8,21.8 58.2,22.2 58.6,22.6 58.6,23 58.3,23.3 56.6,23.3 55.9,22.6 55.9,21
GND on L1 "L1-GND 27" (solid, pour order 245): 66.1,21.9 66.1,20.3 64.8,20.3 64.7,20.4 64.7,21.7 64.7,21.8 64.8,21.9 66.1,21.9
GND on L1 "L1-GND 28" (solid, pour order 246): 66.1,18.1 64.8,18.1 64.7,18.2 64.7,19.5 64.7,19.6 64.8,19.7 66.1,19.7 66.1,18.1
PHASE1_3V3 on L1 "L1-PHASE1_3V3" (solid, pour order 239): 1.2,15.7 1.3,15.8 3.2,15.8 4.2,14.8 4.2,8.8 2.2,6.7 1.4,6.7 1.4,11.7 1.2,11.9
GND on L1 "L1-GND 29" (solid, pour order 247): 69.2,8.7 69.2,6.7 67.7,6.7 67.5,6.9 67.5,8.5 67.7,8.7
GND on L1 "L1-GND 30" (solid, pour order 248): 62.7,0.6 64.8,0.6 64.9,0.7 64.9,1.5 64.8,1.6 62.7,1.6 62.7,0.6
+VIN on L1 "L1-+VIN 5" (solid, pour order 249): 62.4,6.1 63.9,6.1 64.5,5.5 64.5,3.8 64.1,3.4 61.9,3.4 61.3,4 61.3,4.3 62,5 62.3,5 62.4,5.1
PHASE2_1V5 on L1 "L1-PHASE2_1V5" (solid, remove dead copper, pour order 227): 18 vertices, not listed, extent 63,6.7 69.4,15.7
+1V375 on L1 "L1-+1V375 2" (solid, pour order 148): 3.3,24.7 3.3,21.2 3.4,21.1 10.9,21.1 10.9,22 8.2,24.7
+2V5 on L1 "L1-+2V5" (solid, pour order 241): 63.4,27.8 63.4,20.6 63.1,20.3 59.7,20.3 59.7,22.3 60.1,22.7 60.1,22.9 61.3,24.1 61.3,27.8
+3V3_ETH_AVDDH on L8 (PWR) "L8 (PWR)-+3V3_ETH_AVDDH" (solid, pour order 259): 15.4,39 19.9,39 19.9,33 20.3,33 20.3,30.7 18.6,30.7 18.6,31.6 16.4,31.6 14.6,29.8 12.5,29.8 12.5,34.4 15.4,37.3
+1V2_ETH_DVDDL on L8 (PWR) "L8 (PWR)-+1V2_ETH_DVDDL" (solid, pour order 258): 25 vertices, not listed, extent 1,29.8 15.2,39.4
+1V375 on L8 (PWR) "L8 (PWR)-+1V375" (solid, pour order 261): 21 vertices, not listed, extent 1,9.1 29.8,32.2
+1V375_VDDSOC_IN on L8 (PWR) "L8 (PWR)-+1V375_VDDSOC_IN" (solid, pour order 260): 18.6,30.5 18.6,29.4 17.3,28.1 17.3,26.5 16.7,25.9 16.7,22.1 26.4,22.1 27.1,21.4 29.8,21.4 29.8,22.9 28.8,23.9 28.8,25.4 29.9,26.5 29.9,30.5
+1V5_DDR on L8 (PWR) "L8 (PWR)-+1V5_DDR" (solid, pour order 262): 19 vertices, not listed, extent 1,1 69,39
+2V5 on L7 (PWR) "L7 (PWR)-+2V5" (solid, pour order 256): 37 vertices, not listed, extent 6.3,1 63.6,30.7
+2V5_VDDHIGH_VPH on L7 (PWR) "L7 (PWR)-+2V5_VDDHIGH_VPH" (solid, pour order 253): 23.5,16.3 23.5,18.2 22.2,18.2 21.7,18.7 17.3,18.7 15.9,17.3 14.8,17.3 14.8,15.5 16.3,15.5 16.8,16 18.1,17.3 20.5,17.3 21.5,16.3
+VIN on L7 (PWR) "L7 (PWR)-+VIN" (solid, pour order 257): 24 vertices, not listed, extent 1,1 69,39
+1V2_VDD_ARM_CAP on L7 (PWR) "L7 (PWR)-+1V2_VDD_ARM_CAP" (solid, pour order 254): 17.2,18.9 17.2,20.4 22.2,20.4 22.2,21.9 29.2,21.9 29.2,15.7 25.4,15.7 25.4,16.3 23.7,16.3 23.7,18.4 22.3,18.4 21.8,18.9
+SATA_VP on L7 (PWR) "L7 (PWR)-+SATA_VP" (solid, pour order 255): 22,20.6 17.2,20.6 16.7,21.1 16.7,24.6 18.2,24.6 18.2,25.3 22,25.3
+VDDUSB on L7 (PWR) "L7 (PWR)-+VDDUSB" (solid, pour order 252): 18.3,13.2 20.5,15.4 21,15.4 21,16.5 20.4,17.1 18.2,17.1 16.4,15.3 14.8,15.3 14.8,13.2
+PCIE_VPH on L7 (PWR) "L7 (PWR)-+PCIE_VPH" (solid, pour order 250): 21.8,13 20.4,11.6 20.4,8.9 17.9,8.9 17.9,13 18.4,13 20.6,15.2 21.6,15.2 21.8,15
+PCIE_VPTX on L7 (PWR) "L7 (PWR)-+PCIE_VPTX" (solid, pour order 251): 22,12.9 20.6,11.5 20.6,8.9 23.5,8.9 23.5,11 25.2,12.7 25.2,16.1 21.2,16.1 21.2,15.4 21.7,15.4 22,15.1
+2V5_ETH_DVDDH on L5 (PWR) "L5 (PWR)-+2V5_ETH_DVDDH" (solid, pour order 264): 21 vertices, not listed, extent 7.3,24 23.5,39.4
+5V_USB_VBUS on L5 (PWR) "L5 (PWR)-+5V_USB_VBUS" (solid, pour order 153): 21 vertices, not listed, extent 12.7,16.6 32.5,39
+1V2_ETH on L5 (PWR) "L5 (PWR)-+1V2_ETH" (solid, pour order 265): 17 vertices, not listed, extent 1,9.9 16.5,39
+DDR_VREF on L5 (PWR) "L5 (PWR)-+DDR_VREF" (solid, pour order 159): 62.1,29.4 65.8,29.4 65.8,32.2 65.3,32.7 61.6,32.7 61.6,29.9
+1V1_VDDSOC_CAP on L5 (PWR) "L5 (PWR)-+1V1_VDDSOC_CAP" (solid, pour order 156): 25 vertices, not listed, extent 15.5,7.3 48.2,39
+3V0_ALWAYS on L5 (PWR) "L5 (PWR)-+3V0_ALWAYS" (solid, pour order 263): 46 vertices, not listed, extent 1,1 69,26.6
+3V3 on L6 (PWR) "L6 (PWR)-+3V3" (solid, pour order 266): 1,39 1,1 69,1 69,39 1,39
GND on L2 "L2-GND" (solid, pour order 269): 0.1,0.1 0.1,39.9 69.9,39.9 69.9,0.1 0.1,0.1
GND on L11 "L11-GND" (solid, pour order 271): 0.1,39.9 0.1,0.1 69.9,0.1 69.9,39.9 0.1,39.9
GND on L4 (split plane): 69.898,0.102 0.102,0.102 0.102,39.898 69.898,39.898
GND on L9 (split plane): 69.898,0.102 0.102,0.102 0.102,39.898 69.898,39.898

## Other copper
L12:
  text "MM" at 4.9,27.2 h1
  text "(c) FEDEVEL 2013" at 54.45,19.85 h1.05

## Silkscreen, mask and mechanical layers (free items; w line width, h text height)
Top Overlay:
  text "FEDEVEL Academy" at 38.9,20.6 h1.15
  text "www.iMX6Rex.com" at 39.4,18 h1.15
Bottom Overlay:
  lines w0.2: 40.45,17 40.45,19 ; 43.2,17 43.2,19 ; 45.95,17 45.95,19 ; 48.7,17 48.7,19 ; 37.7,17 37.7,19 51.45,19 51.45,17 37.7,17
  text "J1" at 38.8,29.4 h1.15
  text "iMX6 Rex V1I1" at 53.25,21.75 h1.15
  text "E" at 39.45,17.5 h1.15
  text "D" at 42.2,17.5 h1.15
  text "C" at 44.95,17.5 h1.15
  text "B" at 47.7,17.5 h1.15
  text "A" at 50.45,17.5 h1.15
  text "MOD" at 55.3,17.4 h1.15
  text "J2" at 38.8,9.4 h1.15
Bottom Solder:
  text "(c) FEDEVEL 2013" at 54.45,19.85 h1.05
Mechanical Drawing:
  circle w0.6: c67.5,2.5 r1.1
  circle w0.6: c2.5,2.5 r1.1
  circle w0.6: c67.5,37.5 r1.1
  circle w0.6: c2.5,37.5 r1.1
  circle w0.2: c17.935,7.47 r0.5
  circle w0.2: c17.935,37.87 r0.5
  circle w0.2: c38.065,37.87 r0.525
  circle w0.2: c38.065,7.47 r0.5
  lines w0.6: 67.9,40 70,40 70,0 0,0 0,40 0.5,40 69.9,40
  text "Mechanical Drawing of iMX6 Rex Module" at 3.3,47.5 h1.52
  text ".VersionRevision" at 60.8,47.5 h1.52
